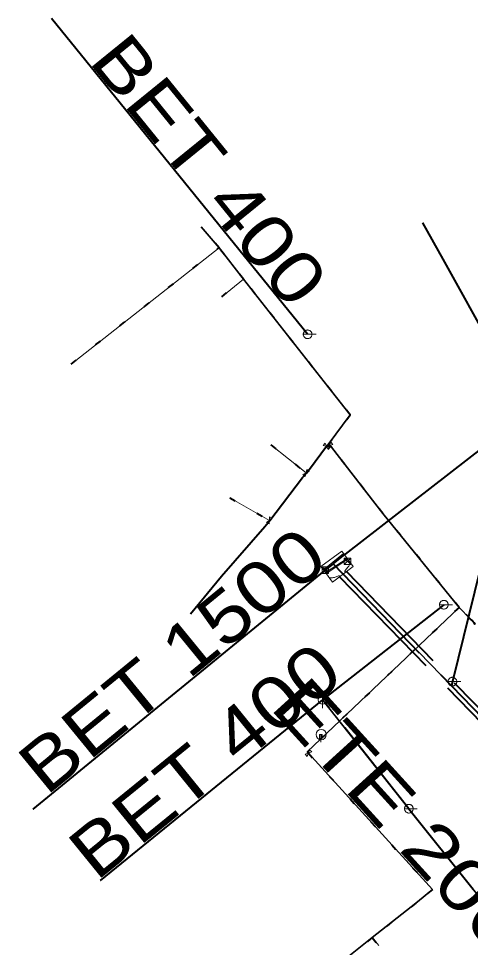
# Model space of a CAD drawing. Extents: x -968691 to -140888, y -1376050 to -879856.
# Drawn here: x -648116.2 to -648011.1, y -1059058.6 to -1058842.6 of the extents above; entities that cross this region are included whole.
import ezdxf
from ezdxf.enums import TextEntityAlignment as Align

# ---------------------------------------------------------------- set-up
doc = ezdxf.new("R2010")
doc.units = 0
doc.header["$LTSCALE"] = 4.8
doc.header["$PDMODE"] = 32
doc.header["$PDSIZE"] = 2.4
for name, pattern in [('DASH_DOUBLE_DOT', [9.2, 5, -1.2, 0.3, -1.2, 0.3, -1.2]), ('DOTTED', [1.5, 0.3, -1.2]), ('LONG_DASHED', [7.5, 6, -1.5]), ('MEDIUM_DASHED', [4.5, 3, -1.5])]:
    doc.linetypes.add(name, pattern=pattern)
doc.layers.add('1', color=7, linetype='Continuous', lineweight=13)

msp = doc.modelspace()

# ---------------------------------------------------------------- linework, layer by layer
at = {"layer": '1', "lineweight": 40}
for p, q in [((-648048.998, -1058916.006), (-648108.593, -1058842.576)), ((-648022.27, -1058890.07), (-648017.573, -1058898.536)), ((-648017.573, -1058898.536), (-648005.02, -1058921.16)), ((-648006.343, -1058960.239), (-648015.319, -1058996.768)), ((-648043.087, -1058969.367), (-648040.24, -1058967.12)), ((-648043.087, -1058969.367), (-648045.13, -1058970.98)), ((-648045.13, -1058970.98), (-648112.91, -1059026.43)), ((-648017.31, -1058978.89), (-648045.548, -1059000.983)), ((-648015.319, -1058996.768), (-648015.562, -1058997.758)), ((-648045.548, -1059000.983), (-648097.28, -1059043.03))]:
    msp.add_line(p, q, dxfattribs=at)
at = {"layer": '1', "lineweight": 35}
for p, q in [((-648048.998, -1058916.006), (-648108.593, -1058842.576)), ((-648069.61, -1058895.93), (-648073.785, -1058891.037)), ((-648022.27, -1058890.07), (-648017.573, -1058898.536)), ((-648063.924, -1058903.168), (-648069.61, -1058895.93)), ((-648017.573, -1058898.536), (-648005.02, -1058921.16)), ((-648043.472, -1058929.201), (-648063.924, -1058903.168)), ((-648044.575, -1058942.029), (-648044.192, -1058941.637)), ((-648044.192, -1058941.637), (-648043.906, -1058941.878)), ((-648043.906, -1058941.878), (-648043.463, -1058942.282)), ((-648006.343, -1058960.239), (-648015.319, -1058996.768)), ((-648043.087, -1058969.367), (-648040.24, -1058967.12)), ((-648043.087, -1058969.367), (-648045.13, -1058970.98)), ((-648043.087, -1058969.367), (-648015.562, -1058997.758)), ((-648045.13, -1058970.98), (-648112.91, -1059026.43)), ((-648017.31, -1058978.89), (-648045.548, -1059000.983)), ((-648015.319, -1058996.768), (-648015.562, -1058997.758)), ((-648015.562, -1058997.758), (-648000.295, -1059013.505)), ((-648045.548, -1059000.983), (-648097.28, -1059043.03)), ((-648025.456, -1059026.328), (-648045.548, -1059000.983)), ((-648025.456, -1059026.328), (-648007.21, -1059049.14)), ((-648033.973, -1059056.289), (-648062.083, -1059078.656))]:
    msp.add_line(p, q, dxfattribs=at)
at = {"layer": '1', "linetype": 'DOTTED', "lineweight": 40}
for p, q in [((-648069.61, -1058895.93), (-648073.785, -1058891.037)), ((-648103.988, -1058922.911), (-648069.61, -1058895.93)), ((-648063.924, -1058903.168), (-648069.61, -1058895.93)), ((-648068.955, -1058907.3), (-648063.924, -1058903.168)), ((-648043.472, -1058929.201), (-648063.924, -1058903.168)), ((-648011.159, -1058982.21), (-648013.767, -1058979.5)), ((-648033.973, -1059056.289), (-648062.083, -1059078.656)), ((-648033.973, -1059056.289), (-648032.47, -1059058.157))]:
    msp.add_line(p, q, dxfattribs=at)
at = {"layer": '1'}
for p, q in [((-648103.988, -1058922.911), (-648069.61, -1058895.93)), ((-648068.955, -1058907.3), (-648063.924, -1058903.168)), ((-648050.006, -1058916.006), (-648047.029, -1058916.006)), ((-648018.318, -1058978.89), (-648015.341, -1058978.89)), ((-648016.327, -1058996.768), (-648013.35, -1058996.768)), ((-648045.548, -1058999.975), (-648045.548, -1059002.951)), ((-648045.852, -1059009.104), (-648045.95, -1059009.104)), ((-648045.95, -1059010.882), (-648045.95, -1059009.104)), ((-648045.803, -1059009.327), (-648045.803, -1059009.768)), ((-648026.464, -1059026.328), (-648023.487, -1059026.328)), ((-648033.973, -1059056.289), (-648032.47, -1059058.157))]:
    msp.add_line(p, q, dxfattribs=at)
at = {"layer": '1', "linetype": 'DASH_DOUBLE_DOT', "lineweight": 40}
for p, q in [((-648044.575, -1058942.029), (-648044.192, -1058941.637)), ((-648044.192, -1058941.637), (-648043.906, -1058941.878)), ((-648043.906, -1058941.878), (-648043.463, -1058942.282)), ((-648025.456, -1059026.328), (-648045.548, -1059000.983)), ((-648025.456, -1059026.328), (-648007.21, -1059049.14))]:
    msp.add_line(p, q, dxfattribs=at)
at = {"layer": '1', "linetype": 'LONG_DASHED'}
for p, q in [((-648045.892, -1058970.034), (-648041.068, -1058966.416)), ((-648038.38, -1058970), (-648041.068, -1058966.416)), ((-648039.772, -1058968.144), (-648044.842, -1058971.434)), ((-648039.652, -1058968.304), (-648044.722, -1058971.594)), ((-648045.892, -1058970.034), (-648045.388, -1058970.706)), ((-648040.196, -1058971.362), (-648040.316, -1058971.202)), ((-648041.476, -1058972.322), (-648041.596, -1058972.162))]:
    msp.add_line(p, q, dxfattribs=at)
at = {"layer": '1', "linetype": 'LONG_DASHED', "lineweight": 40}
for p, q in [((-648043.087, -1058969.367), (-648015.562, -1058997.758)), ((-648039.943, -1058971.172), (-647999.558, -1059012.827)), ((-648041.556, -1058972.382), (-648001.03, -1059014.182)), ((-648015.562, -1058997.758), (-648000.295, -1059013.505))]:
    msp.add_line(p, q, dxfattribs=at)
at = {"layer": '1', "linetype": 'MEDIUM_DASHED'}
for p, q in [((-648038.97, -1058968.04), (-648040.47, -1058969.54)), ((-648040.47, -1058968.04), (-648038.97, -1058969.54)), ((-648044.153, -1058970.117), (-648045.653, -1058971.617)), ((-648045.653, -1058970.117), (-648044.153, -1058971.617))]:
    msp.add_line(p, q, dxfattribs=at)
at = {"layer": '1', "lineweight": 40}
msp.add_lwpolyline([(-647925.54, -1058877.26), (-647966.516, -1058908.451), (-647997.616, -1058933.606), (-648003.99, -1058939.03), (-648040.24, -1058967.12)], dxfattribs=at)
at = {"layer": '1', "lineweight": 35}
for points in [[(-647925.54, -1058877.26), (-647966.516, -1058908.451), (-647997.616, -1058933.606), (-648003.99, -1058939.03), (-648040.24, -1058967.12)], [(-648044.192, -1058941.637), (-648039.101, -1058934.764), (-648043.472, -1058929.201)], [(-648049.281, -1058948.298), (-648047.227, -1058945.584), (-648044.575, -1058942.029)], [(-648013.767, -1058979.5), (-648031.51, -1058957.7), (-648043.463, -1058942.282)], [(-648057.816, -1058959.332), (-648050.169, -1058949.269), (-648049.281, -1058948.298)], [(-648076.26, -1058981.019), (-648069.039, -1058972.236), (-648058.946, -1058960.71), (-648057.816, -1058959.332)], [(-648013.767, -1058979.5), (-648049.098, -1059013.124), (-648048.819, -1059013.413)], [(-648010.025, -1058983.473), (-648010.257, -1058983.113), (-648010.476, -1058982.857), (-648010.758, -1058982.566), (-648011.159, -1058982.21), (-648013.767, -1058979.5)], [(-648048.819, -1059013.413), (-648019.983, -1059045.115), (-648023.82, -1059048.28), (-648033.973, -1059056.289)]]:
    msp.add_lwpolyline(points, dxfattribs=at)
at = {"layer": '1'}
for points in [[(-648048.998, -1058914.998), (-648049.103, -1058915.004), (-648049.207, -1058915.02), (-648049.309, -1058915.047), (-648049.407, -1058915.085), (-648049.501, -1058915.133), (-648049.589, -1058915.19), (-648049.672, -1058915.257), (-648049.747, -1058915.332), (-648049.813, -1058915.414), (-648049.87, -1058915.501), (-648049.917, -1058915.596), (-648049.955, -1058915.695), (-648049.983, -1058915.796), (-648049.999, -1058915.901), (-648050.006, -1058916.006), (-648049.999, -1058916.111), (-648049.983, -1058916.216), (-648049.955, -1058916.318), (-648049.917, -1058916.416), (-648049.87, -1058916.509), (-648049.813, -1058916.599), (-648049.747, -1058916.681), (-648049.672, -1058916.755), (-648049.589, -1058916.821), (-648049.501, -1058916.879), (-648049.407, -1058916.927), (-648049.309, -1058916.965), (-648049.207, -1058916.992), (-648049.103, -1058917.008), (-648048.998, -1058917.014), (-648048.892, -1058917.008), (-648048.787, -1058916.992), (-648048.686, -1058916.965), (-648048.588, -1058916.927), (-648048.493, -1058916.879), (-648048.405, -1058916.821), (-648048.323, -1058916.755), (-648048.248, -1058916.681), (-648048.182, -1058916.599), (-648048.125, -1058916.509), (-648048.076, -1058916.416), (-648048.038, -1058916.318), (-648048.012, -1058916.216), (-648047.996, -1058916.111), (-648047.99, -1058916.006), (-648047.996, -1058915.901), (-648048.012, -1058915.796), (-648048.038, -1058915.695), (-648048.076, -1058915.596), (-648048.125, -1058915.501), (-648048.182, -1058915.414), (-648048.248, -1058915.332), (-648048.323, -1058915.257), (-648048.405, -1058915.19), (-648048.493, -1058915.133), (-648048.588, -1058915.085), (-648048.686, -1058915.047), (-648048.787, -1058915.02), (-648048.892, -1058915.004)], [(-648043.77, -1058942.22), (-648044.204, -1058942.769), (-648044.946, -1058941.289), (-648045.38, -1058941.838)], [(-648043.608, -1058941.106), (-648043.123, -1058941.61), (-648044.689, -1058942.146), (-648044.204, -1058942.65)], [(-648049.161, -1058947.432), (-648048.616, -1058947.872), (-648050.102, -1058948.6), (-648049.557, -1058949.04)], [(-648057.851, -1058958.456), (-648057.236, -1058958.791), (-648058.57, -1058959.773), (-648057.955, -1058960.108)], [(-648040.47, -1058969.54), (-648038.97, -1058969.54), (-648038.97, -1058968.04), (-648040.47, -1058968.04)], [(-648045.653, -1058971.617), (-648044.153, -1058971.617), (-648044.153, -1058970.117), (-648045.653, -1058970.117)], [(-648017.31, -1058977.882), (-648017.415, -1058977.888), (-648017.519, -1058977.904), (-648017.621, -1058977.931), (-648017.719, -1058977.969), (-648017.813, -1058978.017), (-648017.901, -1058978.074), (-648017.984, -1058978.141), (-648018.059, -1058978.216), (-648018.125, -1058978.298), (-648018.182, -1058978.385), (-648018.229, -1058978.48), (-648018.267, -1058978.579), (-648018.295, -1058978.68), (-648018.311, -1058978.785), (-648018.318, -1058978.89), (-648018.311, -1058978.995), (-648018.295, -1058979.1), (-648018.267, -1058979.202), (-648018.229, -1058979.3), (-648018.182, -1058979.393), (-648018.125, -1058979.483), (-648018.059, -1058979.565), (-648017.984, -1058979.639), (-648017.901, -1058979.705), (-648017.813, -1058979.763), (-648017.719, -1058979.811), (-648017.621, -1058979.849), (-648017.519, -1058979.876), (-648017.415, -1058979.892), (-648017.31, -1058979.898), (-648017.204, -1058979.892), (-648017.099, -1058979.876), (-648016.998, -1058979.849), (-648016.9, -1058979.811), (-648016.805, -1058979.763), (-648016.717, -1058979.705), (-648016.635, -1058979.639), (-648016.56, -1058979.565), (-648016.494, -1058979.483), (-648016.437, -1058979.393), (-648016.388, -1058979.3), (-648016.35, -1058979.202), (-648016.324, -1058979.1), (-648016.308, -1058978.995), (-648016.302, -1058978.89), (-648016.308, -1058978.785), (-648016.324, -1058978.68), (-648016.35, -1058978.579), (-648016.388, -1058978.48), (-648016.437, -1058978.385), (-648016.494, -1058978.298), (-648016.56, -1058978.216), (-648016.635, -1058978.141), (-648016.717, -1058978.074), (-648016.805, -1058978.017), (-648016.9, -1058977.969), (-648016.998, -1058977.931), (-648017.099, -1058977.904), (-648017.204, -1058977.888)], [(-648015.319, -1058995.76), (-648015.424, -1058995.766), (-648015.528, -1058995.782), (-648015.63, -1058995.809), (-648015.728, -1058995.847), (-648015.822, -1058995.895), (-648015.91, -1058995.952), (-648015.993, -1058996.019), (-648016.068, -1058996.094), (-648016.134, -1058996.176), (-648016.191, -1058996.263), (-648016.238, -1058996.358), (-648016.276, -1058996.457), (-648016.304, -1058996.558), (-648016.32, -1058996.663), (-648016.327, -1058996.768), (-648016.32, -1058996.873), (-648016.304, -1058996.978), (-648016.276, -1058997.08), (-648016.238, -1058997.178), (-648016.191, -1058997.271), (-648016.134, -1058997.361), (-648016.068, -1058997.443), (-648015.993, -1058997.517), (-648015.91, -1058997.583), (-648015.822, -1058997.641), (-648015.728, -1058997.689), (-648015.63, -1058997.727), (-648015.528, -1058997.754), (-648015.424, -1058997.77), (-648015.319, -1058997.776), (-648015.213, -1058997.77), (-648015.108, -1058997.754), (-648015.007, -1058997.727), (-648014.909, -1058997.689), (-648014.814, -1058997.641), (-648014.726, -1058997.583), (-648014.644, -1058997.517), (-648014.569, -1058997.443), (-648014.503, -1058997.361), (-648014.446, -1058997.271), (-648014.397, -1058997.178), (-648014.359, -1058997.08), (-648014.333, -1058996.978), (-648014.317, -1058996.873), (-648014.311, -1058996.768), (-648014.317, -1058996.663), (-648014.333, -1058996.558), (-648014.359, -1058996.457), (-648014.397, -1058996.358), (-648014.446, -1058996.263), (-648014.503, -1058996.176), (-648014.569, -1058996.094), (-648014.644, -1058996.019), (-648014.726, -1058995.952), (-648014.814, -1058995.895), (-648014.909, -1058995.847), (-648015.007, -1058995.809), (-648015.108, -1058995.782), (-648015.213, -1058995.766)], [(-648044.54, -1059000.983), (-648044.546, -1059000.878), (-648044.562, -1059000.774), (-648044.59, -1059000.672), (-648044.628, -1059000.573), (-648044.675, -1059000.479), (-648044.733, -1059000.391), (-648044.799, -1059000.309), (-648044.874, -1059000.234), (-648044.956, -1059000.168), (-648045.044, -1059000.11), (-648045.138, -1059000.063), (-648045.237, -1059000.025), (-648045.339, -1058999.997), (-648045.443, -1058999.981), (-648045.548, -1058999.975), (-648045.653, -1058999.981), (-648045.758, -1058999.997), (-648045.86, -1059000.025), (-648045.958, -1059000.063), (-648046.052, -1059000.11), (-648046.141, -1059000.168), (-648046.223, -1059000.234), (-648046.297, -1059000.309), (-648046.363, -1059000.391), (-648046.421, -1059000.479), (-648046.469, -1059000.573), (-648046.507, -1059000.672), (-648046.534, -1059000.774), (-648046.55, -1059000.878), (-648046.556, -1059000.983), (-648046.55, -1059001.088), (-648046.534, -1059001.193), (-648046.507, -1059001.295), (-648046.469, -1059001.393), (-648046.421, -1059001.487), (-648046.363, -1059001.576), (-648046.297, -1059001.658), (-648046.223, -1059001.732), (-648046.141, -1059001.798), (-648046.052, -1059001.856), (-648045.958, -1059001.904), (-648045.86, -1059001.942), (-648045.758, -1059001.969), (-648045.653, -1059001.985), (-648045.548, -1059001.991), (-648045.443, -1059001.985), (-648045.339, -1059001.969), (-648045.237, -1059001.942), (-648045.138, -1059001.904), (-648045.044, -1059001.856), (-648044.956, -1059001.798), (-648044.874, -1059001.732), (-648044.799, -1059001.658), (-648044.733, -1059001.576), (-648044.675, -1059001.487), (-648044.628, -1059001.393), (-648044.59, -1059001.295), (-648044.562, -1059001.193), (-648044.546, -1059001.088)], [(-648046.251, -1059009.993), (-648045.649, -1059009.993), (-648045.649, -1059009.104), (-648046.251, -1059009.104)], [(-648045.873, -1059009.874), (-648045.726, -1059009.874), (-648045.726, -1059009.208), (-648045.873, -1059009.208)], [(-648049.112, -1059014.187), (-648049.601, -1059013.685), (-648048.037, -1059013.141), (-648048.526, -1059012.639)], [(-648025.456, -1059025.32), (-648025.561, -1059025.326), (-648025.665, -1059025.342), (-648025.767, -1059025.369), (-648025.865, -1059025.407), (-648025.959, -1059025.455), (-648026.047, -1059025.512), (-648026.13, -1059025.579), (-648026.205, -1059025.654), (-648026.271, -1059025.736), (-648026.328, -1059025.823), (-648026.375, -1059025.918), (-648026.413, -1059026.017), (-648026.441, -1059026.118), (-648026.457, -1059026.223), (-648026.464, -1059026.328), (-648026.457, -1059026.433), (-648026.441, -1059026.538), (-648026.413, -1059026.64), (-648026.375, -1059026.738), (-648026.328, -1059026.831), (-648026.271, -1059026.921), (-648026.205, -1059027.003), (-648026.13, -1059027.077), (-648026.047, -1059027.143), (-648025.959, -1059027.201), (-648025.865, -1059027.249), (-648025.767, -1059027.287), (-648025.665, -1059027.314), (-648025.561, -1059027.33), (-648025.456, -1059027.336), (-648025.35, -1059027.33), (-648025.245, -1059027.314), (-648025.144, -1059027.287), (-648025.046, -1059027.249), (-648024.951, -1059027.201), (-648024.863, -1059027.143), (-648024.781, -1059027.077), (-648024.706, -1059027.003), (-648024.64, -1059026.921), (-648024.583, -1059026.831), (-648024.534, -1059026.738), (-648024.496, -1059026.64), (-648024.47, -1059026.538), (-648024.454, -1059026.433), (-648024.448, -1059026.328), (-648024.454, -1059026.223), (-648024.47, -1059026.118), (-648024.496, -1059026.017), (-648024.534, -1059025.918), (-648024.583, -1059025.823), (-648024.64, -1059025.736), (-648024.706, -1059025.654), (-648024.781, -1059025.579), (-648024.863, -1059025.512), (-648024.951, -1059025.455), (-648025.046, -1059025.407), (-648025.144, -1059025.369), (-648025.245, -1059025.342), (-648025.35, -1059025.326)]]:
    msp.add_lwpolyline(points, close=True, dxfattribs=at)
at = {"layer": '1', "linetype": 'DOTTED', "lineweight": 40}
for points in [[(-648044.192, -1058941.637), (-648039.101, -1058934.764), (-648043.472, -1058929.201)], [(-648057.538, -1058941.713), (-648049.359, -1058948.236), (-648049.281, -1058948.298)], [(-648013.767, -1058979.5), (-648031.51, -1058957.7), (-648043.463, -1058942.282)], [(-648067.074, -1058954.022), (-648057.903, -1058959.282), (-648057.816, -1058959.332)], [(-648013.767, -1058979.5), (-648049.098, -1059013.124), (-648048.819, -1059013.413)], [(-648048.819, -1059013.413), (-648019.983, -1059045.115), (-648023.82, -1059048.28), (-648033.973, -1059056.289)]]:
    msp.add_lwpolyline(points, dxfattribs=at)
at = {"layer": '1'}
for points in [[(-648057.538, -1058941.713), (-648049.359, -1058948.236), (-648049.281, -1058948.298)], [(-648067.074, -1058954.022), (-648057.903, -1058959.282), (-648057.816, -1058959.332)]]:
    msp.add_lwpolyline(points, dxfattribs=at)
at = {"layer": '1', "linetype": 'DASH_DOUBLE_DOT', "lineweight": 40}
for points in [[(-648049.281, -1058948.298), (-648047.227, -1058945.584), (-648044.575, -1058942.029)], [(-648057.816, -1058959.332), (-648050.169, -1058949.269), (-648049.281, -1058948.298)], [(-648076.26, -1058981.019), (-648069.039, -1058972.236), (-648058.946, -1058960.71), (-648057.816, -1058959.332)], [(-648010.025, -1058983.473), (-648010.257, -1058983.113), (-648010.476, -1058982.857), (-648010.758, -1058982.566), (-648011.159, -1058982.21)]]:
    msp.add_lwpolyline(points, dxfattribs=at)
at = {"layer": '1', "linetype": 'LONG_DASHED'}
for points in [[(-648045.322, -1058970.794), (-648043.103, -1058968.987), (-648040.672, -1058966.944)], [(-648040.316, -1058971.202), (-648040.319, -1058971.165), (-648040.319, -1058971.118), (-648040.297, -1058971.045), (-648040.246, -1058970.962), (-648039.621, -1058970.181), (-648039.443, -1058969.916), (-648039.299, -1058969.62), (-648039.191, -1058969.297), (-648039.13, -1058969)], [(-648044.36, -1058971.06), (-648044.9, -1058970.34), (-648045.388, -1058970.706)], [(-648045.388, -1058970.706), (-648044.86, -1058971.41), (-648044.36, -1058971.06)], [(-648044.86, -1058971.41), (-648043.204, -1058973.618), (-648038.38, -1058970)], [(-648043.954, -1058972.618), (-648043.718, -1058972.623), (-648043.457, -1058972.618), (-648043.233, -1058972.607), (-648043.003, -1058972.578), (-648042.771, -1058972.543), (-648041.846, -1058972.162), (-648041.791, -1058972.147), (-648041.746, -1058972.142), (-648041.701, -1058972.142), (-648041.657, -1058972.146), (-648041.619, -1058972.155), (-648041.596, -1058972.162)]]:
    msp.add_lwpolyline(points, dxfattribs=at)
at = {"layer": '1'}
for centre in [(-648044.575, -1058942.029), (-648043.906, -1058941.878), (-648049.359, -1058948.236), (-648057.903, -1058959.282), (-648048.819, -1059013.413)]:
    msp.add_circle(centre, 0.132, dxfattribs=at)
msp.add_point((-648045.852, -1059009.104), dxfattribs=at)

# ---------------------------------------------------------------- texts
for s, rotation, width, p in [('BET 400', 309.062, 1.2, (-648076.548, -1058881.583)), ('BET 1500', 39.286, 1.2, (-648076.716, -1058996.433)), ('BET 400', 39.104, 1.2, (-648069.119, -1059019.755)), ('ETE 200', 312.29, 1.25, (-648031.769, -1059031.711))]:
    msp.add_text(s, height=12, rotation=rotation, dxfattribs=dict(at, width=width)).set_placement(p, align=Align.CENTER)

doc.saveas('drawing.dxf')
